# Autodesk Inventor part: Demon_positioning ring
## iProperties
Shininess: 64.0
Length Units: 11269
Angle Units: 11279
Time Units: 11290
Mass Units: 11283
Length Display Precision: 3
Angle Display Precision: 2
Compacted: True
Part Number: Demon_positioning ring
Document SubType Name: Modeling
Created: 2005-04
Material: Aluminum-6061
Designer: John Blackburn
Manufacturer: Standard
Standards Organization: Custom
Density: 0.0
Volumn: 0.0
Area: 0.0
PropertySet Name: Model Information
Control State: 0
Master: False
Checked Out: False
Author: John Blackburn
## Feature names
1. Extrusion1
